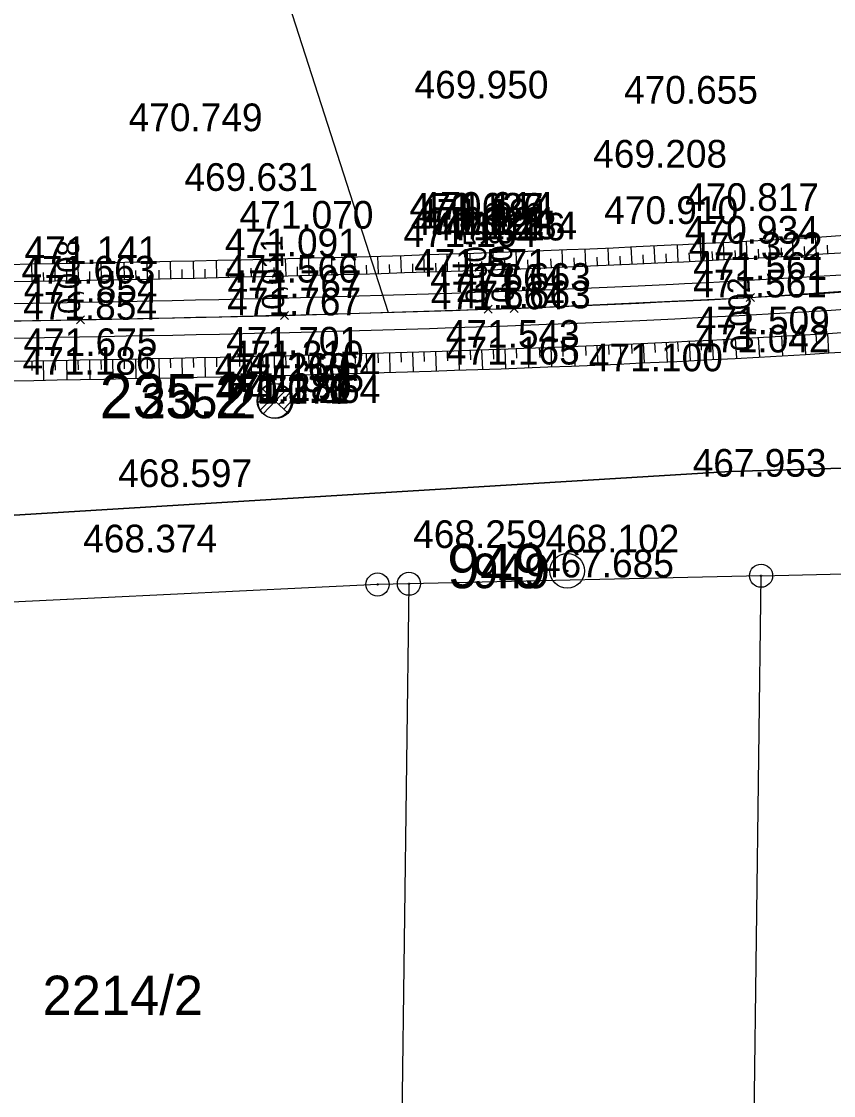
# Model space of a CAD drawing. Extents: x -758836 to -757729, y -1175316 to -1174366.
# Drawn here: x -758173.42 to -758138.23, y -1174797.31 to -1174750.75 of the extents above; entities that cross this region are included whole.
import ezdxf

# ---------------------------------------------------------------- set-up
doc = ezdxf.new("R2010")
doc.units = 0
for name, color, linetype in [('_NOR-body-stávající osa', 7, 'Continuous'), ('_NOR-návrh tenká', 7, 'Continuous'), ('_NOR-osa', 7, 'Continuous'), ('_NOR-popis', 7, 'Continuous'), ('_NOR-posuny', 7, 'Continuous'), ('_NOR-svahy', 7, 'Continuous'), ('G_Obvod stavby', 7, 'Continuous'), ('Hranice parcel', 7, 'Continuous'), ('Parcelní čísla', 7, 'Continuous'), ('Vrstva 1', 7, 'Continuous'), ('Vrstva 61', 7, 'Continuous'), ('Vrstva 63', 7, 'Continuous'), ('Značky bodu BP', 7, 'Continuous')]:
    doc.layers.add(name, color=color, linetype=linetype)

# ---------------------------------------------------------------- blocks, each defined once
blk = doc.blocks.new('C003')
at = {"layer": 'Vrstva 63'}
for p, q in [((-0.762, -0.063), (-0.348, 0.351)), ((-0.661, -0.386), (-0.138, 0.137)), ((0.147, -0.15), (0.667, 0.37)), ((0.359, -0.362), (0.763, 0.041))]:
    blk.add_line(p, q, dxfattribs=at)
for points in [[(-0.536, 0.542), (0, -0.003), (-0.541, -0.544)], [(0, -0.003), (0.541, 0.538)], [(0.541, -0.544), (0, -0.003)]]:
    blk.add_lwpolyline(points, dxfattribs=at)
blk.add_circle((0, -0.003), 0.764, dxfattribs=at)
for centre, start, end in [((0.001, -0.003), 134.6025, 224.9205), ((-0.001, -0.003), 315.0532, 44.9468)]:
    blk.add_arc(centre, 0.765, start, end, dxfattribs=at)
blk = doc.blocks.new('POINT_DISPLAY')
for p, q in [((-0.175, -0.175), (0.175, 0.175)), ((-0.175, 0.175), (0.175, -0.175))]:
    blk.add_line(p, q)

msp = doc.modelspace()

# ---------------------------------------------------------------- linework, layer by layer
at = {"layer": '_NOR-návrh tenká'}
for points in [[(-758173.987, -1174761.281), (-758172.977, -1174761.263), (-758171.968, -1174761.245), (-758170.958, -1174761.226), (-758169.949, -1174761.207), (-758168.94, -1174761.187), (-758167.93, -1174761.167), (-758166.921, -1174761.146), (-758165.913, -1174761.124), (-758164.904, -1174761.102), (-758163.895, -1174761.079), (-758162.887, -1174761.055), (-758161.879, -1174761.031), (-758160.871, -1174761.005), (-758159.863, -1174760.978), (-758158.855, -1174760.95), (-758157.848, -1174760.921), (-758156.84, -1174760.891), (-758155.833, -1174760.86), (-758154.826, -1174760.827), (-758153.819, -1174760.793), (-758152.813, -1174760.758), (-758151.806, -1174760.721), (-758150.8, -1174760.682), (-758149.794, -1174760.642), (-758148.788, -1174760.601), (-758147.782, -1174760.558), (-758146.778, -1174760.513), (-758145.268, -1174760.441), (-758144.767, -1174760.417), (-758143.762, -1174760.367), (-758142.758, -1174760.314), (-758141.753, -1174760.259), (-758140.749, -1174760.203), (-758139.746, -1174760.144), (-758138.742, -1174760.083), (-758137.739, -1174760.02)], [(-758173.974, -1174762.031), (-758172.964, -1174762.013), (-758171.954, -1174761.994), (-758170.944, -1174761.976), (-758169.934, -1174761.957), (-758168.925, -1174761.937), (-758167.915, -1174761.917), (-758166.906, -1174761.896), (-758165.896, -1174761.874), (-758164.887, -1174761.852), (-758163.878, -1174761.829), (-758162.869, -1174761.805), (-758161.86, -1174761.78), (-758160.851, -1174761.755), (-758159.843, -1174761.728), (-758158.834, -1174761.7), (-758157.826, -1174761.671), (-758156.818, -1174761.641), (-758155.809, -1174761.609), (-758154.801, -1174761.577), (-758153.794, -1174761.543), (-758152.786, -1174761.507), (-758151.778, -1174761.47), (-758150.771, -1174761.432), (-758149.764, -1174761.392), (-758148.757, -1174761.35), (-758147.75, -1174761.307), (-758146.743, -1174761.262), (-758145.232, -1174761.191), (-758144.73, -1174761.166), (-758143.724, -1174761.116), (-758142.718, -1174761.063), (-758141.712, -1174761.008), (-758140.706, -1174760.952), (-758139.701, -1174760.893), (-758138.696, -1174760.832), (-758137.691, -1174760.768)], [(-758173.957, -1174762.981), (-758172.947, -1174762.963), (-758171.937, -1174762.944), (-758170.926, -1174762.926), (-758169.916, -1174762.906), (-758168.906, -1174762.887), (-758167.896, -1174762.866), (-758166.886, -1174762.846), (-758165.876, -1174762.824), (-758164.866, -1174762.802), (-758163.856, -1174762.779), (-758162.846, -1174762.755), (-758161.836, -1174762.73), (-758160.827, -1174762.704), (-758159.817, -1174762.677), (-758158.807, -1174762.65), (-758157.798, -1174762.621), (-758156.789, -1174762.59), (-758155.779, -1174762.559), (-758154.77, -1174762.526), (-758153.761, -1174762.492), (-758152.752, -1174762.457), (-758151.743, -1174762.42), (-758150.734, -1174762.381), (-758149.725, -1174762.341), (-758148.716, -1174762.299), (-758147.708, -1174762.256), (-758146.7, -1174762.211), (-758145.187, -1174762.139), (-758144.683, -1174762.115), (-758143.675, -1174762.064), (-758142.667, -1174762.012), (-758141.659, -1174761.957), (-758140.652, -1174761.9), (-758139.644, -1174761.841), (-758138.637, -1174761.78), (-758137.63, -1174761.716)], [(-758173.931, -1174764.48), (-758172.92, -1174764.462), (-758171.909, -1174764.444), (-758170.898, -1174764.425), (-758169.887, -1174764.406), (-758168.876, -1174764.386), (-758167.865, -1174764.366), (-758166.854, -1174764.345), (-758165.843, -1174764.324), (-758164.832, -1174764.301), (-758163.821, -1174764.278), (-758162.81, -1174764.254), (-758161.799, -1174764.23), (-758160.788, -1174764.204), (-758159.776, -1174764.177), (-758158.765, -1174764.149), (-758157.754, -1174764.12), (-758156.743, -1174764.09), (-758155.732, -1174764.058), (-758154.72, -1174764.025), (-758153.709, -1174763.991), (-758152.698, -1174763.956), (-758151.687, -1174763.919), (-758150.676, -1174763.88), (-758149.664, -1174763.84), (-758148.653, -1174763.798), (-758147.642, -1174763.755), (-758146.631, -1174763.709), (-758145.115, -1174763.638), (-758144.609, -1174763.613), (-758143.598, -1174763.562), (-758142.587, -1174763.509), (-758141.576, -1174763.455), (-758140.566, -1174763.398), (-758139.555, -1174763.338), (-758138.544, -1174763.277), (-758137.534, -1174763.213)], [(-758173.913, -1174765.48), (-758172.902, -1174765.462), (-758171.891, -1174765.444), (-758170.879, -1174765.425), (-758169.868, -1174765.406), (-758168.857, -1174765.386), (-758167.845, -1174765.366), (-758166.833, -1174765.345), (-758165.822, -1174765.323), (-758164.81, -1174765.301), (-758163.798, -1174765.278), (-758162.786, -1174765.254), (-758161.774, -1174765.229), (-758160.762, -1174765.203), (-758159.749, -1174765.176), (-758158.737, -1174765.149), (-758157.725, -1174765.119), (-758156.712, -1174765.089), (-758155.7, -1174765.058), (-758154.687, -1174765.025), (-758153.675, -1174764.991), (-758152.662, -1174764.955), (-758151.649, -1174764.918), (-758150.637, -1174764.879), (-758149.624, -1174764.839), (-758148.611, -1174764.797), (-758147.598, -1174764.754), (-758146.585, -1174764.708), (-758145.067, -1174764.637), (-758144.56, -1174764.612), (-758143.547, -1174764.561), (-758142.534, -1174764.508), (-758141.521, -1174764.453), (-758140.508, -1174764.396), (-758139.496, -1174764.337), (-758138.483, -1174764.275), (-758137.47, -1174764.211)], [(-758173.898, -1174766.33), (-758172.887, -1174766.312), (-758171.875, -1174766.294), (-758170.864, -1174766.275), (-758169.852, -1174766.256), (-758168.84, -1174766.236), (-758167.828, -1174766.216), (-758166.815, -1174766.195), (-758165.803, -1174766.173), (-758164.791, -1174766.151), (-758163.778, -1174766.128), (-758162.765, -1174766.104), (-758161.752, -1174766.079), (-758160.739, -1174766.053), (-758159.726, -1174766.026), (-758158.713, -1174765.998), (-758157.7, -1174765.969), (-758156.686, -1174765.939), (-758155.673, -1174765.907), (-758154.659, -1174765.874), (-758153.645, -1174765.84), (-758152.632, -1174765.804), (-758151.618, -1174765.767), (-758150.604, -1174765.729), (-758149.589, -1174765.688), (-758148.575, -1174765.646), (-758147.561, -1174765.603), (-758146.546, -1174765.557), (-758145.027, -1174765.486), (-758144.518, -1174765.461), (-758143.503, -1174765.41), (-758142.489, -1174765.357), (-758141.474, -1174765.302), (-758140.46, -1174765.245), (-758139.445, -1174765.185), (-758138.43, -1174765.124), (-758137.416, -1174765.06)]]:
    msp.add_lwpolyline(points, dxfattribs=at)
at = {"layer": '_NOR-osa'}
msp.add_lwpolyline([(-758173.944, -1174763.73), (-758172.933, -1174763.712), (-758171.923, -1174763.694), (-758170.912, -1174763.675), (-758169.902, -1174763.656), (-758168.891, -1174763.637), (-758167.881, -1174763.616), (-758166.87, -1174763.595), (-758165.859, -1174763.574), (-758164.849, -1174763.552), (-758163.838, -1174763.529), (-758162.828, -1174763.505), (-758161.818, -1174763.48), (-758160.807, -1174763.454), (-758159.797, -1174763.427), (-758158.786, -1174763.399), (-758157.776, -1174763.37), (-758156.766, -1174763.34), (-758155.755, -1174763.309), (-758154.745, -1174763.276), (-758153.735, -1174763.242), (-758152.725, -1174763.206), (-758151.715, -1174763.169), (-758150.705, -1174763.131), (-758149.695, -1174763.09), (-758148.685, -1174763.049), (-758147.675, -1174763.005), (-758146.665, -1174762.96), (-758145.656, -1174762.913), (-758144.646, -1174762.864), (-758143.637, -1174762.813), (-758142.627, -1174762.761), (-758141.618, -1174762.706), (-758140.609, -1174762.649), (-758139.6, -1174762.59), (-758138.591, -1174762.528), (-758137.582, -1174762.465)], dxfattribs=at)
at = {"layer": '_NOR-popis'}
msp.add_lwpolyline([(-758169.12, -1174696.384), (-758178.163, -1174699.297), (-758157.527, -1174763.363)], dxfattribs=at)
at = {"layer": '_NOR-svahy'}
for points in [[(-758141.968, -1174761.022), (-758142.009, -1174760.273)], [(-758140.97, -1174760.966), (-758141.012, -1174760.218)], [(-758139.971, -1174760.909), (-758140.015, -1174760.16)], [(-758138.973, -1174760.849), (-758139.018, -1174760.1)], [(-758152.957, -1174761.513), (-758152.983, -1174760.764)], [(-758151.958, -1174761.477), (-758151.985, -1174760.727)], [(-758150.958, -1174761.439), (-758150.987, -1174760.69)], [(-758149.959, -1174761.4), (-758149.989, -1174760.65)], [(-758148.96, -1174761.359), (-758148.991, -1174760.609)], [(-758147.961, -1174761.316), (-758147.993, -1174760.567)], [(-758146.962, -1174761.272), (-758146.995, -1174760.522)], [(-758145.963, -1174761.225), (-758145.998, -1174760.476)], [(-758144.964, -1174761.178), (-758145, -1174760.428)], [(-758143.965, -1174761.128), (-758144.003, -1174760.379)], [(-758143.466, -1174761.102), (-758143.485, -1174760.728)], [(-758142.967, -1174761.076), (-758143.006, -1174760.327)], [(-758142.467, -1174761.049), (-758142.488, -1174760.675)], [(-758141.469, -1174760.995), (-758141.49, -1174760.62)], [(-758140.47, -1174760.938), (-758140.492, -1174760.563)], [(-758139.472, -1174760.879), (-758139.495, -1174760.505)], [(-758138.474, -1174760.818), (-758138.498, -1174760.444)], [(-758170.951, -1174761.976), (-758170.965, -1174761.226)], [(-758169.951, -1174761.957), (-758169.965, -1174761.207)], [(-758168.951, -1174761.937), (-758168.966, -1174761.188)], [(-758167.951, -1174761.917), (-758167.966, -1174761.168)], [(-758166.951, -1174761.897), (-758166.967, -1174761.147)], [(-758165.952, -1174761.875), (-758165.968, -1174761.126)], [(-758164.952, -1174761.853), (-758164.968, -1174761.104)], [(-758163.952, -1174761.831), (-758163.969, -1174761.081)], [(-758162.952, -1174761.807), (-758162.97, -1174761.057)], [(-758161.953, -1174761.783), (-758161.971, -1174761.033)], [(-758160.953, -1174761.757), (-758160.972, -1174761.007)], [(-758159.953, -1174761.731), (-758159.973, -1174760.981)], [(-758158.954, -1174761.703), (-758158.975, -1174760.954)], [(-758157.954, -1174761.675), (-758157.976, -1174760.925)], [(-758156.955, -1174761.645), (-758156.977, -1174760.895)], [(-758155.955, -1174761.614), (-758155.979, -1174760.864)], [(-758155.455, -1174761.598), (-758155.468, -1174761.223)], [(-758154.956, -1174761.582), (-758154.98, -1174760.832)], [(-758154.456, -1174761.565), (-758154.469, -1174761.19)], [(-758153.956, -1174761.548), (-758153.982, -1174760.799)], [(-758153.457, -1174761.531), (-758153.47, -1174761.156)], [(-758152.457, -1174761.495), (-758152.471, -1174761.12)], [(-758151.458, -1174761.458), (-758151.472, -1174761.083)], [(-758150.459, -1174761.419), (-758150.474, -1174761.045)], [(-758149.459, -1174761.379), (-758149.475, -1174761.005)], [(-758148.46, -1174761.337), (-758148.476, -1174760.963)], [(-758147.461, -1174761.294), (-758147.478, -1174760.919)], [(-758146.462, -1174761.249), (-758146.48, -1174760.874)], [(-758145.463, -1174761.201), (-758145.481, -1174760.827)], [(-758144.465, -1174761.153), (-758144.483, -1174760.778)], [(-758172.95, -1174762.013), (-758172.964, -1174761.263)], [(-758172.45, -1174762.003), (-758172.457, -1174761.629)], [(-758171.951, -1174761.994), (-758171.964, -1174761.245)], [(-758171.451, -1174761.985), (-758171.458, -1174761.61)], [(-758170.451, -1174761.966), (-758170.458, -1174761.591)], [(-758169.451, -1174761.947), (-758169.458, -1174761.572)], [(-758168.451, -1174761.927), (-758168.459, -1174761.552)], [(-758167.451, -1174761.907), (-758167.459, -1174761.532)], [(-758166.452, -1174761.886), (-758166.46, -1174761.511)], [(-758165.452, -1174761.864), (-758165.46, -1174761.49)], [(-758164.452, -1174761.842), (-758164.461, -1174761.467)], [(-758163.452, -1174761.819), (-758163.461, -1174761.444)], [(-758162.453, -1174761.795), (-758162.462, -1174761.42)], [(-758161.453, -1174761.77), (-758161.463, -1174761.395)], [(-758160.453, -1174761.744), (-758160.463, -1174761.369)], [(-758159.454, -1174761.717), (-758159.464, -1174761.342)], [(-758158.454, -1174761.689), (-758158.465, -1174761.314)], [(-758157.454, -1174761.66), (-758157.466, -1174761.285)], [(-758156.455, -1174761.63), (-758156.467, -1174761.255)], [(-758141.99, -1174764.479), (-758141.967, -1174764.903)], [(-758141.491, -1174764.451), (-758141.443, -1174765.3)], [(-758140.991, -1174764.423), (-758140.967, -1174764.848)], [(-758140.492, -1174764.395), (-758140.443, -1174765.244)], [(-758139.993, -1174764.366), (-758139.968, -1174764.79)], [(-758139.494, -1174764.337), (-758139.442, -1174765.185)], [(-758138.995, -1174764.306), (-758138.969, -1174764.73)], [(-758138.496, -1174764.276), (-758138.444, -1174765.124)], [(-758152.979, -1174764.966), (-758152.964, -1174765.391)], [(-758152.479, -1174764.948), (-758152.448, -1174765.798)], [(-758151.98, -1174764.93), (-758151.964, -1174765.355)], [(-758151.48, -1174764.911), (-758151.447, -1174765.761)], [(-758150.98, -1174764.892), (-758150.964, -1174765.317)], [(-758150.481, -1174764.873), (-758150.447, -1174765.722)], [(-758149.981, -1174764.853), (-758149.964, -1174765.278)], [(-758149.481, -1174764.833), (-758149.446, -1174765.682)], [(-758148.982, -1174764.812), (-758148.964, -1174765.237)], [(-758148.482, -1174764.792), (-758148.446, -1174765.641)], [(-758147.983, -1174764.77), (-758147.964, -1174765.195)], [(-758147.483, -1174764.748), (-758147.445, -1174765.598)], [(-758146.984, -1174764.726), (-758146.965, -1174765.151)], [(-758146.484, -1174764.703), (-758146.444, -1174765.553)], [(-758145.985, -1174764.68), (-758145.965, -1174765.104)], [(-758145.485, -1174764.656), (-758145.445, -1174765.505)], [(-758144.986, -1174764.633), (-758144.965, -1174765.057)], [(-758144.487, -1174764.608), (-758144.444, -1174765.457)], [(-758143.987, -1174764.583), (-758143.966, -1174765.008)], [(-758143.488, -1174764.558), (-758143.443, -1174765.407)], [(-758142.988, -1174764.532), (-758142.966, -1174764.956)], [(-758142.489, -1174764.506), (-758142.443, -1174765.354)], [(-758170.973, -1174765.427), (-758170.965, -1174765.852)], [(-758170.473, -1174765.417), (-758170.457, -1174766.267)], [(-758169.973, -1174765.408), (-758169.965, -1174765.833)], [(-758169.473, -1174765.398), (-758169.457, -1174766.248)], [(-758168.973, -1174765.389), (-758168.965, -1174765.813)], [(-758168.473, -1174765.379), (-758168.456, -1174766.228)], [(-758167.973, -1174765.369), (-758167.965, -1174765.793)], [(-758167.473, -1174765.358), (-758167.456, -1174766.208)], [(-758166.974, -1174765.348), (-758166.965, -1174765.773)], [(-758166.474, -1174765.337), (-758166.456, -1174766.187)], [(-758165.974, -1174765.327), (-758165.965, -1174765.752)], [(-758165.474, -1174765.316), (-758165.455, -1174766.166)], [(-758164.974, -1174765.305), (-758164.965, -1174765.73)], [(-758164.474, -1174765.293), (-758164.455, -1174766.143)], [(-758163.974, -1174765.282), (-758163.965, -1174765.707)], [(-758163.474, -1174765.27), (-758163.454, -1174766.12)], [(-758162.975, -1174765.259), (-758162.965, -1174765.683)], [(-758162.475, -1174765.246), (-758162.454, -1174766.096)], [(-758161.975, -1174765.234), (-758161.964, -1174765.659)], [(-758161.475, -1174765.222), (-758161.453, -1174766.071)], [(-758160.975, -1174765.209), (-758160.964, -1174765.634)], [(-758160.475, -1174765.196), (-758160.453, -1174766.045)], [(-758159.976, -1174765.183), (-758159.964, -1174765.607)], [(-758159.476, -1174765.169), (-758159.452, -1174766.019)], [(-758158.976, -1174765.155), (-758158.964, -1174765.58)], [(-758158.476, -1174765.141), (-758158.452, -1174765.991)], [(-758157.976, -1174765.127), (-758157.964, -1174765.552)], [(-758157.477, -1174765.112), (-758157.451, -1174765.962)], [(-758156.977, -1174765.097), (-758156.964, -1174765.522)], [(-758156.477, -1174765.082), (-758156.451, -1174765.931)], [(-758155.977, -1174765.066), (-758155.964, -1174765.491)], [(-758155.477, -1174765.05), (-758155.45, -1174765.9)], [(-758154.978, -1174765.034), (-758154.964, -1174765.459)], [(-758154.478, -1174765.018), (-758154.449, -1174765.867)], [(-758153.978, -1174765.001), (-758153.964, -1174765.426)], [(-758153.479, -1174764.984), (-758153.449, -1174765.833)], [(-758172.972, -1174765.463), (-758172.965, -1174765.888)], [(-758172.473, -1174765.454), (-758172.457, -1174766.304)], [(-758171.973, -1174765.445), (-758171.965, -1174765.87)], [(-758171.473, -1174765.436), (-758171.457, -1174766.286)]]:
    msp.add_lwpolyline(points, dxfattribs=at)
at = {"layer": 'G_Obvod stavby'}
msp.add_lwpolyline([(-758392.72, -1174840.756), (-758391.23, -1174838.56), (-758368.37, -1174821.64), (-758340.31, -1174807.33), (-758320.27, -1174796.89), (-758301, -1174790.21), (-758267.96, -1174782.93), (-758224.96, -1174775.27), (-758184.87, -1174772.83), (-758142.71, -1174770.26), (-758089.84, -1174768.68), (-758106.02, -1174731.44), (-758149.09, -1174725.67), (-758199.62, -1174726.6), (-758225.76, -1174732.36), (-758252.17, -1174738.18), (-758254.97, -1174739.34), (-758266.58, -1174744.16), (-758279.45, -1174749.49), (-758302.42, -1174759.02), (-758331.68, -1174770.24), (-758367.17, -1174799.81), (-758405.64, -1174832.2)], dxfattribs=at)
at = {"layer": 'Hranice parcel'}
for p, q in [((-758141.37, -1174774.78), (-758125.97, -1174774.42)), ((-758156.63, -1174775.13), (-758157.87, -1174870.96)), ((-758141.37, -1174774.78), (-758156.63, -1174775.13)), ((-758143.14, -1174911.79), (-758141.37, -1174774.78))]:
    msp.add_line(p, q, dxfattribs=at)
for points in [[(-757877.73, -1174631.24), (-757883.07, -1174637.8), (-757892.39, -1174640.95), (-757964.85, -1174709.42), (-757976.05, -1174741.17), (-757981.89, -1174745.86), (-757990.29, -1174747.68), (-757997.69, -1174745.08), (-758004.14, -1174738), (-758040.32, -1174755.99), (-758089.84, -1174768.68), (-758142.71, -1174770.26), (-758184.87, -1174772.83)], [(-758156.63, -1174775.13), (-758157.99, -1174775.16), (-758184.92, -1174776.46)]]:
    msp.add_lwpolyline(points, dxfattribs=at)
at = {"layer": 'Vrstva 1'}
msp.add_lwpolyline([(-758275.047, -1174773.289), (-758265.484, -1174771.118), (-758253.61, -1174768.888), (-758243.69, -1174767.426), (-758231.371, -1174766.042), (-758219.363, -1174765.122), (-758206.915, -1174764.505), (-758194.225, -1174764.118), (-758182.013, -1174763.871), (-758170.862, -1174763.683), (-758162.019, -1174763.496), (-758153.195, -1174763.228), (-758152.069, -1174763.19), (-758141.836, -1174762.716), (-758130.402, -1174761.933), (-758120.726, -1174760.981), (-758108.612, -1174759.398), (-758096.467, -1174757.277), (-758085.591, -1174754.917)], dxfattribs=at)
at = {"layer": 'Značky bodu BP'}
for centre, radius in [((-758162.46, -1174767.2), 0.75), ((-758162.46, -1174767.2), 0.03), ((-758149.77, -1174774.57), 0.75), ((-758141.37, -1174774.78), 0.5), ((-758157.99, -1174775.16), 0.5), ((-758156.63, -1174775.13), 0.5), ((-758149.77, -1174774.57), 0.03), ((-758157.99, -1174775.16), 0.0303), ((-758156.63, -1174775.13), 0.0303), ((-758141.37, -1174774.78), 0.0303)]:
    msp.add_circle(centre, radius, dxfattribs=at)

# ---------------------------------------------------------------- block references
at = {"layer": '_NOR-body-stávající osa'}
for p in [(-758141.836, -1174762.716), (-758153.195, -1174763.228), (-758152.069, -1174763.19), (-758170.862, -1174763.683), (-758162.019, -1174763.496)]:
    msp.add_blockref('POINT_DISPLAY', p, dxfattribs=at)
at = {"layer": 'Vrstva 63', "rotation": 1.2114343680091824}
msp.add_blockref('C003', (-758162.421, -1174767.204), dxfattribs=at)

# ---------------------------------------------------------------- texts
at = {"layer": '_NOR-posuny'}
for s, rotation, p in [('0,005', 92.0147, (-758153.204, -1174762.973)), ('0,008', 92.0981, (-758152.078, -1174762.932)), ('0,008', 91.0613, (-758170.867, -1174763.425)), ('0,011', 91.408, (-758162.026, -1174763.235)), ('0,002', 93.1092, (-758141.711, -1174765.018))]:
    msp.add_text(s, height=0.9599, rotation=rotation, dxfattribs=at).set_placement(p)
at = {"layer": 'Parcelní čísla'}
msp.add_text('2214/2', height=1.7, dxfattribs=at).set_placement((-758172.505, -1174793.82))
at = {"layer": 'Vrstva 61'}
for s, p in [('469.950', (-758156.385, -1174754.09)), ('470.655', (-758147.309, -1174754.314)), ('470.749', (-758168.774, -1174755.507)), ('469.208', (-758148.644, -1174757.086)), ('469.631', (-758166.358, -1174758.096)), ('470.817', (-758144.663, -1174758.964)), ('470.627', (-758156.603, -1174759.383)), ('471.126', (-758156.592, -1174759.385)), ('471.191', (-758156.316, -1174759.644)), ('470.614', (-758156.166, -1174759.348)), ('471.114', (-758156.161, -1174759.349)), ('470.910', (-758148.167, -1174759.531)), ('471.070', (-758163.969, -1174759.733)), ('471.123', (-758156.566, -1174760.007)), ('470.922', (-758156.558, -1174760.008)), ('471.124', (-758156.131, -1174759.991)), ('470.924', (-758156.131, -1174759.991)), ('471.164', (-758156.871, -1174760.531)), ('471.116', (-758155.644, -1174760.246)), ('471.134', (-758155.14, -1174760.196)), ('470.934', (-758144.67, -1174760.382)), ('471.091', (-758164.602, -1174760.937)), ('471.141', (-758173.283, -1174761.271)), ('471.322', (-758144.508, -1174761.089)), ('471.571', (-758156.407, -1174761.818)), ('471.561', (-758144.312, -1174761.956)), ('471.663', (-758173.421, -1174762.113)), ('471.566', (-758164.606, -1174762.07)), ('471.663', (-758154.549, -1174762.429)), ('471.767', (-758164.485, -1174762.744)), ('471.664', (-758155.704, -1174762.476)), ('471.561', (-758144.321, -1174762.716)), ('471.854', (-758173.321, -1174762.942)), ('471.664', (-758155.68, -1174763.228)), ('471.663', (-758154.554, -1174763.19)), ('471.854', (-758173.347, -1174763.683)), ('471.767', (-758164.504, -1174763.496)), ('471.509', (-758144.195, -1174764.312)), ('471.701', (-758164.547, -1174765.192)), ('471.543', (-758155.031, -1174764.899)), ('471.042', (-758144.207, -1174765.102)), ('471.675', (-758173.331, -1174765.256)), ('471.165', (-758155.029, -1174765.623)), ('471.186', (-758173.367, -1174766.066)), ('471.310', (-758164.391, -1174765.793)), ('471.100', (-758148.83, -1174765.917)), ('471.260', (-758165.034, -1174766.332)), ('471.264', (-758163.686, -1174766.313)), ('471.305', (-758164.375, -1174766.818)), ('471.270', (-758165.005, -1174767.316)), ('470.371', (-758165, -1174767.317)), ('471.289', (-758164.906, -1174767.204)), ('470.364', (-758163.674, -1174767.288)), ('471.264', (-758163.668, -1174767.288)), ('467.953', (-758144.336, -1174770.486)), ('468.597', (-758169.228, -1174770.934)), ('468.259', (-758156.443, -1174773.578)), ('468.374', (-758170.742, -1174773.767)), ('468.102', (-758150.715, -1174773.772)), ('467.685', (-758150.951, -1174774.852))]:
    msp.add_text(s, height=1.2, dxfattribs=at).set_placement(p)
at = {"layer": 'Značky bodu BP'}
for s, height, p in [('235.2', 1.9192, (-758170.03, -1174767.95)), ('235.2', 1.5, (-758168.28, -1174767.95)), ('949', 1.9192, (-758154.972, -1174775.32)), ('949', 1.5, (-758153.873, -1174775.32))]:
    msp.add_text(s, height=height, dxfattribs=at).set_placement(p)

doc.saveas('drawing.dxf')
